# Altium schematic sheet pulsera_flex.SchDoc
size A; SheetNumber: 1; SheetTotal: 1
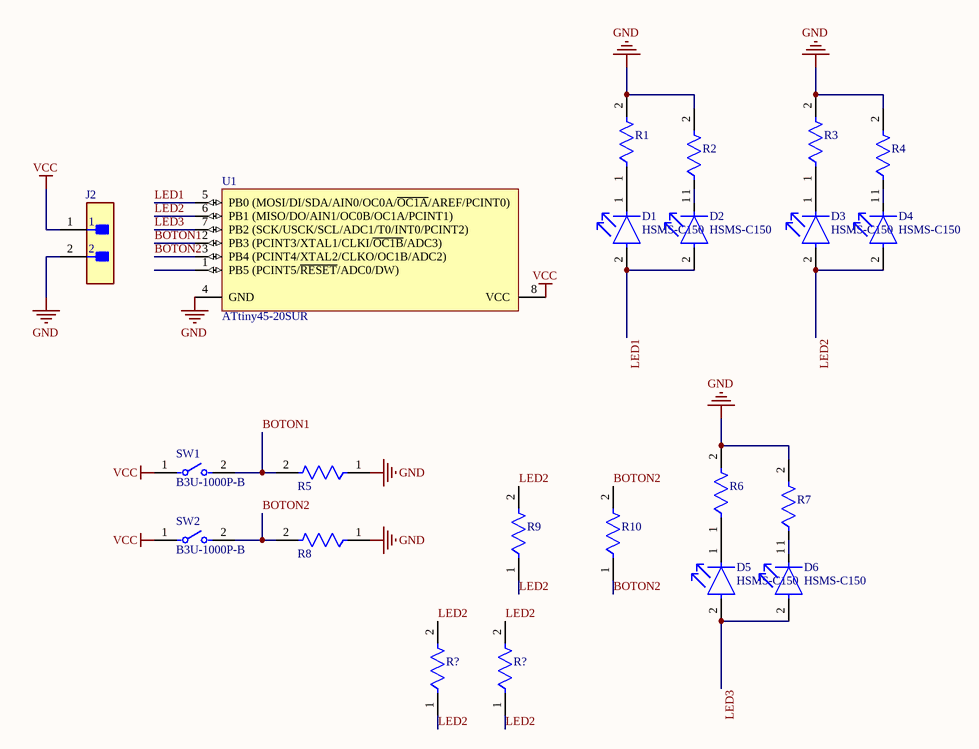
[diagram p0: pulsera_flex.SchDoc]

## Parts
(Parts that share a designator on the sheet are numbered #1, #2 ... from top to bottom, then left to right.)
D1  HSMS-C150  [FP-HSMS-C150-MFG]
D2  HSMS-C150  [FP-HSMS-C150-MFG]
D3  HSMS-C150  [FP-HSMS-C150-MFG]
D4  HSMS-C150  [FP-HSMS-C150-MFG]
D5  HSMS-C150  [FP-HSMS-C150-MFG]
D6  HSMS-C150  [FP-HSMS-C150-MFG]
J2  M20-9990246  [FP-M20-9990246-MFG]  (value not drawn)
R1  RC1206JR-070RL  [FP-RC1206-MFG]  (value not drawn)
R2  RC1206JR-070RL  [FP-RC1206-MFG]  (value not drawn)
R3  RC1206JR-070RL  [FP-RC1206-MFG]  (value not drawn)
R4  RC1206JR-070RL  [FP-RC1206-MFG]  (value not drawn)
R5  RC1206JR-070RL  [FP-RC1206-MFG]  (value not drawn)
R6  RC1206JR-070RL  [FP-RC1206-MFG]  (value not drawn)
R7  RC1206JR-070RL  [FP-RC1206-MFG]  (value not drawn)
R8  RC1206JR-070RL  [FP-RC1206-MFG]  (value not drawn)
R9  RC1206JR-070RL  [FP-RC1206-MFG]  (value not drawn)
R10  RC1206JR-070RL  [FP-RC1206-MFG]  (value not drawn)
R?#1  RC1206JR-070RL  [FP-RC1206-MFG]  (value not drawn)
R?#2  RC1206JR-070RL  [FP-RC1206-MFG]  (value not drawn)
SW1  B3U-1000P-B  [FP-B3U-1000P-B-MFG]
SW2  B3U-1000P-B  [FP-B3U-1000P-B-MFG]
U1  ATtiny45-20SUR  [8S2_L]

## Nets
GND: J2.2 R1.2 R2.2 R3.2 R4.2 R5.1 R6.2 R7.2 R8.1 U1.4(GND)
VCC: J2.1 SW1.1 SW2.1 U1.8(VCC)
BOTON1: R5.2 SW1.2 U1.2(PB3_(PCINT3/XTAL1/CLKI/~{OC1B}/ADC3))
BOTON2: R8.2 R10.1 R10.2 SW2.2 U1.3(PB4_(PCINT4/XTAL2/CLKO/OC1B/ADC2))
LED1: D1.2(A) D2.2(A) U1.5(PB0_(MOSI/DI/SDA/AIN0/OC0A/~{OC1A}/AREF/PCINT0))
LED2: D3.2(A) D4.2(A) R9.1 R9.2 R?#1.1 R?#1.2 R?#2.1 R?#2.2 U1.6(PB1_(MISO/DO/AIN1/OC0B/OC1A/PCINT1))
LED3: D5.2(A) D6.2(A) U1.7(PB2_(SCK/USCK/SCL/ADC1/T0/INT0/PCINT2))
NetD1_1: D1.1(C) R1.1
NetD2_1: D2.1(C) R2.1
NetD3_1: D3.1(C) R3.1
NetD4_1: D4.1(C) R4.1
NetD5_1: D5.1(C) R6.1
NetD6_1: D6.1(C) R7.1

Not connected (* = marked no-connect by the designer): U1 1(PB5_(PCINT5/~{RESET}/ADC0/DW))

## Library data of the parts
D1-D6 = CMP-21615-000001-1: LED RED DIFFUSED CHIP SMD; Luminous Intensity: 10mcd; Power Dissipation: 65mW; Viewing Angle: 170°; Number of Elements: 1; Forward Current: 20mA; Lens Color: White; Lens Style: Rectangular; Wavelength: 626nm; Forward Voltage: 2.1V; Reverse Voltage: 5V
J2 = CMP-15831-000009-1: CONN HEADER VERT 2POS 2.54MM; Manufacturer: Harwin; Conn Gender: Male; Conn Orientation: Vertical; Number Of Contacts: 2; Current Rating: 3A
R1-R10 R?#1 R?#2 = CMP-2100-03681-2: RES SMD 0 OHM JUMPER 1/4W 1206; Manufacturer: YAGEO; Voltage Rating: 200V; Temperature Coefficient: 300ppm/°C; Power Rating: 0.25W; Value: 0Ω; Tolerance: 5%
SW1 SW2 = CMP-08834-000005-1: SWITCH TACTILE SPST-NO 0.05A 12V; Manufacturer: Omron; Description: Tactile Switch SPST-NO Top Actuated Surface Mount; Operating Force: 1.5N; Contact Current Rating: 50mA; Contact Resistance: 100mΩ; Electromechanical Life: 200000Cycles
U1 = CMP-0093-00355-1: 8-bit AVR Microcontroller, 20MHz, 2.7-5.5V, 4K Flash, 256 Bytes EEPROM, 256 Bytes SRAM, Industrial Grade (-40°C to 85°C), 8-Lead SOIC, Pb-Free, Reel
